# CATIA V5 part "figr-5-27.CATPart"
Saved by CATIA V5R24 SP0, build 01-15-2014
Part number: Part1
Bounding box of the stored display mesh (mm): x -34.542 to 34.542, y -63.781 to 63.781, z 0 to 53
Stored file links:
  D:\KAVITA\CATIA V5-6R2014 Project_ Kavita\CATIA V5-6R2014_partfiles\Partfiles\c05_catia_v5-6r2014_prt\figr-5-27.CATPart
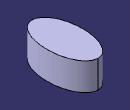
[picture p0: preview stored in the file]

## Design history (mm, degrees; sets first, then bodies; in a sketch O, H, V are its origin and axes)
Body1 (main body)
  Sketch1 on xy-plane, origin (0, 0, 0), H (1, 0, 0), V (0, 1, 0)
    line L1 (-75, 100) -> (75, 100)
    line L2 (75, 100) -> (75, -100)
    line L3 (75, -100) -> (-75, -100)
    line L4 (-75, -100) -> (-75, 100)
    axis line L5 (75, -100) -> (-75, 100)
    length L3 = 150
    length L2 = 200
    horizontal: L1 H, L3 H
    vertical: L2 V, L4 V
    midpoint: L5 O
  Pad1: profile Sketch1, direction (0, 0, 1), length 53
  Sketch2 on face of Pad1, origin (0, 0, 53), H (1, 0, 0), V (0, 1, 0)
    ellipse A1 centre (0, 0) semi-axes 63.781, 34.5424 rotation 270
    point P1 (0, -63.781)
    point P2 (34.5424, 0)
    coincidence: P1 V, P2 H, A1 P1, A1 P2
  Pocket1: profile Sketch2, direction (0, 0, -1), through (limit type 3), outer side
